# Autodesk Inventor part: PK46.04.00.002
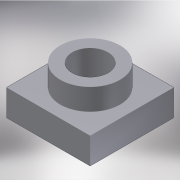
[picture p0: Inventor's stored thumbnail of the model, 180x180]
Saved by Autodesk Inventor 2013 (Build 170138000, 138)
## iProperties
Shininess: 64.0
Length Units: 11269
Angle Units: 11279
Time Units: 11290
Mass Units: 11283
Length Display Precision: 3
Angle Display Precision: 2
Compacted: True
Part Number: PK46.04.00.002
Document SubType Name: Modeling
Created: 2004-12
Material: Steel, Mild
Designer: Salex
Manufacturer: Standard
Standards Organization: Custom
Density: 7.86 g/cm^3
Density: 0.0
Volumn: 0.0
Area: 0.0
PropertySet Name: Model Information
Control State: 0
Master: False
Checked Out: False
Checked Out Date: 2008-10-15
Last Check In Date: 2008-10-15
Author: Salex
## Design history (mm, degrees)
sketch "Sketch1"
  geometry: L1 (0, 0)-(70, 0); L2 (70, 0)-(70, 70); L3 (70, 70)-(0, 70); L4 (0, 70)-(0, 0); C1 r 15 at (35, 35)
  constraints: 8 end point, 2 parallel, 1 centre point, 1 horizontal, 1 perpendicular, 1 other
  dimensions: "d0" = 70 distance of L1.start L1.end; "d1" = 70 distance of L3.end L1.start (= d0); "d2" = 30 diameter of C1; "d3" = 35 distance from line of C1.centre L3 (= 0.5 x d0); "d4" = 35 distance from line of L4 C1.centre (= d3)
extrude "Extrusion1" new body sketch "Sketch1" distance "d5" = 22; taper "d6" = 0 deg
sketch "Sketch2"
  geometry: C1 r 15 at (35, 35) reference; C2 r 25 at (35, 35)
  constraints: 1 centre point, 1 coincident
  dimensions: "d7" = 50 diameter of C2
extrude "Extrusion2" join sketch "Sketch2" distance "d8" = 18; taper "d9" = 0 deg
body "Solid1"
